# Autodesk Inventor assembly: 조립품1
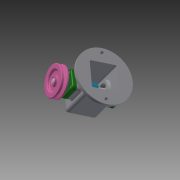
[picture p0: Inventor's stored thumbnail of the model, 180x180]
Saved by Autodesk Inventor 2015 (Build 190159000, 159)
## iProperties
Created: 2021-08
Part Number: 조립품1
Document SubType Name: Assembly
Designer: 103-20
Author: 103-20
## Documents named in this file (16)
- C:\Users\103-20\Desktop\710806V1024 (1)\조립품1.iam
- C:\Users\103-20\Desktop\710806V1024 (1)\V벨트풀리.ipt
- C:\Users\103-20\Desktop\710806V1024 (1)\고정핀 1.2x8.ipt
- C:\Users\103-20\Desktop\710806V1024 (1)\뒤커버.ipt
- C:\Users\103-20\Desktop\710806V1024 (1)\링크.ipt
- C:\Users\103-20\Desktop\710806V1024 (1)\멈춤나사 M3x8.ipt
- C:\Users\103-20\Desktop\710806V1024 (1)\베어링 12x32x10.ipt
- C:\Users\103-20\Desktop\710806V1024 (1)\본체.ipt
- C:\Users\103-20\Desktop\710806V1024 (1)\볼트 M4.ipt
- C:\Users\103-20\Desktop\710806V1024 (1)\부시.ipt
- C:\Users\103-20\Desktop\710806V1024 (1)\슬라이드.ipt
- C:\Users\103-20\Desktop\710806V1024 (1)\앞커버.ipt
- C:\Users\103-20\Desktop\710806V1024 (1)\오일 실 12 25 7.ipt
- C:\Users\103-20\Desktop\710806V1024 (1)\키 4x4x10.ipt
- C:\Users\103-20\Desktop\710806V1024 (1)\편심축.ipt
- C:\Users\103-20\Desktop\710806V1024 (1)\핀 5x18.ipt
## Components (3 placed, 3 different names)
1. V벨트풀리:1 — 플러쉬:5
2. 고정핀 1.2x8:1
3. 핀 5x18:1
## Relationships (1: Flush 1)
- 플러쉬:5 [Flush]: V벨트풀리:1
